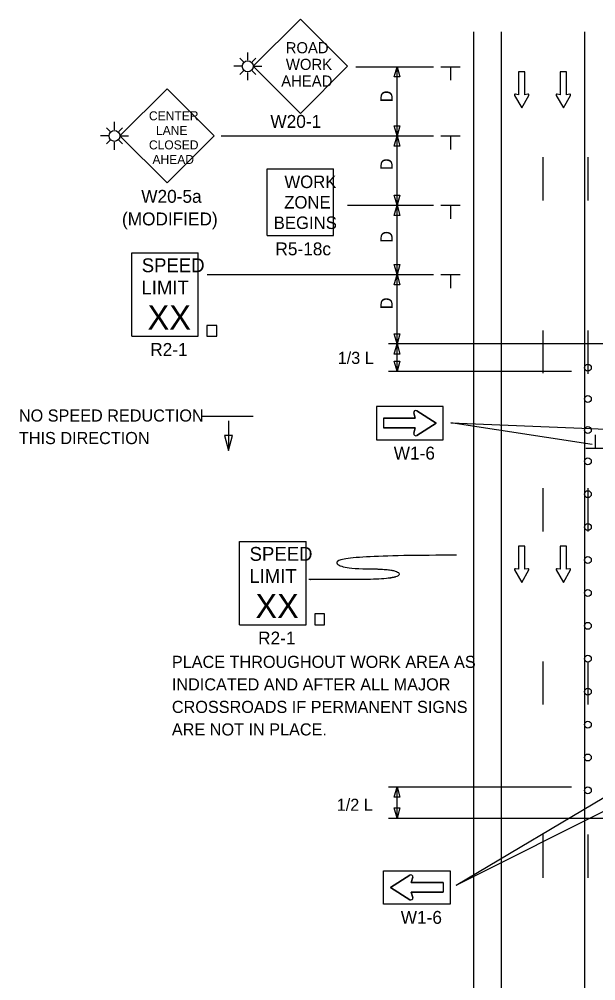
# Model space of a CAD drawing. Extents: x 16525 to 18478, y 5730 to 6925.
# Drawn here: x 16750 to 17082, y 6370 to 6925 of the extents above; entities that cross this region are included whole.
import ezdxf

# ---------------------------------------------------------------- set-up
doc = ezdxf.new("R2010")
doc.units = 0
for name, color, linetype in [('ALI_LEGAL_EX', 7, 'Continuous'), ('Level 3', 7, 'Continuous'), ('MT_SCRATCH_LEVEL_E', 7, 'Continuous'), ('PAVT_EDGE_EX', 7, 'Continuous'), ('TRAFFIC_SIGNS_PR', 7, 'Continuous'), ('TYPICAL_TEXT_DIMEN_PR', 7, 'Continuous')]:
    doc.layers.add(name, color=color, linetype=linetype)

msp = doc.modelspace()

# ---------------------------------------------------------------- linework, layer by layer
at = {"layer": 'ALI_LEGAL_EX'}
for points in [[(17051.59, 6845.22), (17051.59, 6820.22)], [(17077.59, 6845.22), (17077.59, 6820.22)], [(17051.59, 6745.22), (17051.59, 6720.56)], [(17077.59, 6745.22), (17077.59, 6720.22)], [(17051.59, 6654.22), (17051.59, 6629.22)], [(17077.59, 6654.22), (17077.59, 6629.22)], [(17051.59, 6554.22), (17051.59, 6529.22)], [(17077.59, 6554.22), (17077.59, 6529.22)], [(17051.59, 6454.22), (17051.59, 6429.22)], [(17077.59, 6454.22), (17077.59, 6429.22)]]:
    msp.add_lwpolyline(points, dxfattribs=at)
at = {"layer": 'Level 3'}
msp.add_line((17080.12, 6679.35), (16998.62, 6691.92), dxfattribs=at)
at = {"layer": 'MT_SCRATCH_LEVEL_E'}
for p, q in [((17041.26, 6894.53), (17037.52, 6894.53)), ((17037.52, 6894.53), (17037.52, 6881.27)), ((17041.26, 6894.53), (17037.52, 6894.53)), ((17037.52, 6894.53), (17037.52, 6881.27)), ((17041.26, 6881.27), (17041.26, 6894.53)), ((17041.26, 6881.27), (17041.26, 6894.53)), ((17065.33, 6894.53), (17061.59, 6894.53)), ((17061.59, 6894.53), (17061.59, 6881.27)), ((17065.33, 6894.53), (17061.59, 6894.53)), ((17061.59, 6894.53), (17061.59, 6881.27)), ((17065.33, 6881.27), (17065.33, 6894.53)), ((17065.33, 6881.27), (17065.33, 6894.53)), ((17035.26, 6880.9), (17039.41, 6873.66)), ((17035.26, 6880.9), (17039.41, 6873.66)), ((17037.52, 6881.27), (17035.74, 6881.59)), ((17037.52, 6881.27), (17035.74, 6881.59)), ((17039.41, 6873.66), (17043.52, 6880.9)), ((17039.41, 6873.66), (17043.52, 6880.9)), ((17043.03, 6881.59), (17041.26, 6881.27)), ((17043.03, 6881.59), (17041.26, 6881.27)), ((17059.33, 6880.9), (17063.48, 6873.66)), ((17059.33, 6880.9), (17063.48, 6873.66)), ((17061.59, 6881.27), (17059.81, 6881.59)), ((17061.59, 6881.27), (17059.81, 6881.59)), ((17063.48, 6873.66), (17067.59, 6880.9)), ((17063.48, 6873.66), (17067.59, 6880.9)), ((17067.11, 6881.59), (17065.33, 6881.27)), ((17067.11, 6881.59), (17065.33, 6881.27)), ((17041.26, 6620.66), (17037.52, 6620.66)), ((17037.52, 6620.66), (17037.52, 6607.4)), ((17041.26, 6620.66), (17037.52, 6620.66)), ((17037.52, 6620.66), (17037.52, 6607.4)), ((17041.26, 6607.4), (17041.26, 6620.66)), ((17041.26, 6607.4), (17041.26, 6620.66)), ((17065.33, 6620.66), (17061.59, 6620.66)), ((17061.59, 6620.66), (17061.59, 6607.4)), ((17065.33, 6620.66), (17061.59, 6620.66)), ((17061.59, 6620.66), (17061.59, 6607.4)), ((17065.33, 6607.4), (17065.33, 6620.66)), ((17065.33, 6607.4), (17065.33, 6620.66)), ((17035.26, 6607.03), (17039.41, 6599.79)), ((17035.26, 6607.03), (17039.41, 6599.79)), ((17037.52, 6607.4), (17035.74, 6607.72)), ((17037.52, 6607.4), (17035.74, 6607.72)), ((17039.41, 6599.79), (17043.52, 6607.03)), ((17039.41, 6599.79), (17043.52, 6607.03)), ((17043.03, 6607.72), (17041.26, 6607.4)), ((17043.03, 6607.72), (17041.26, 6607.4)), ((17059.33, 6607.03), (17063.48, 6599.79)), ((17059.33, 6607.03), (17063.48, 6599.79)), ((17061.59, 6607.4), (17059.81, 6607.72)), ((17061.59, 6607.4), (17059.81, 6607.72)), ((17063.48, 6599.79), (17067.59, 6607.03)), ((17063.48, 6599.79), (17067.59, 6607.03)), ((17067.11, 6607.72), (17065.33, 6607.4)), ((17067.11, 6607.72), (17065.33, 6607.4))]:
    msp.add_line(p, q, dxfattribs=at)
for centre, start, end in [((17035.67, 6881.13), 80.0362, 209.7731), ((17035.67, 6881.13), 80.0362, 209.7731), ((17043.11, 6881.13), 330.4248, 99.9638), ((17043.11, 6881.13), 330.4248, 99.9638), ((17059.74, 6881.13), 80.0362, 209.7731), ((17059.74, 6881.13), 80.0362, 209.7731), ((17067.18, 6881.13), 330.4248, 99.9638), ((17067.18, 6881.13), 330.4248, 99.9638), ((17035.67, 6607.26), 80.0362, 209.7731), ((17035.67, 6607.26), 80.0362, 209.7731), ((17043.11, 6607.26), 330.4248, 99.9638), ((17043.11, 6607.26), 330.4248, 99.9638), ((17059.74, 6607.26), 80.0362, 209.7731), ((17059.74, 6607.26), 80.0362, 209.7731), ((17067.18, 6607.26), 330.4248, 99.9638), ((17067.18, 6607.26), 330.4248, 99.9638)]:
    msp.add_arc(centre, 0.463, start, end, dxfattribs=at)
at = {"layer": 'PAVT_EDGE_EX'}
for p, q in [((17011.59, 6917.57), (17011.59, 6063.18)), ((17027.59, 6917.57), (17027.59, 6063.18)), ((17075.59, 6917.57), (17075.59, 6063.18))]:
    msp.add_line(p, q, dxfattribs=at)
at = {"layer": 'TRAFFIC_SIGNS_PR'}
for p, q in [((16911.72, 6924.87), (16884.53, 6897.68)), ((16938.9, 6897.68), (16911.72, 6924.87)), ((16881.38, 6901.24), (16881.38, 6905.74)), ((16878.86, 6900.19), (16876.76, 6902.3)), ((16883.89, 6900.19), (16886, 6902.3)), ((16878.22, 6897.68), (16873.39, 6897.68)), ((16878.86, 6895.17), (16876.76, 6893.06)), ((16881.38, 6889.71), (16881.38, 6894.13)), ((16883.89, 6895.17), (16886, 6893.06)), ((16884.53, 6897.68), (16911.72, 6870.49)), ((16884.53, 6897.68), (16889.41, 6897.68)), ((16911.72, 6870.49), (16938.9, 6897.68)), ((16834.77, 6884.67), (16807.62, 6857.51)), ((16861.92, 6857.51), (16834.77, 6884.67)), ((16801.95, 6860.03), (16799.84, 6862.13)), ((16804.47, 6861.07), (16804.47, 6865.57)), ((16806.98, 6860.03), (16809.09, 6862.13)), ((16801.31, 6857.51), (16796.47, 6857.51)), ((16801.95, 6855), (16799.84, 6852.89)), ((16806.98, 6855), (16809.09, 6852.89)), ((16807.62, 6857.51), (16812.5, 6857.51)), ((16807.62, 6857.51), (16834.77, 6830.36)), ((16834.77, 6830.36), (16861.92, 6857.51)), ((16804.47, 6849.55), (16804.47, 6853.96)), ((16892.51, 6800.03), (16892.51, 6838.43)), ((16892.51, 6838.43), (16930.91, 6838.43)), ((16930.91, 6800.03), (16930.91, 6838.43)), ((16892.51, 6800.03), (16930.91, 6800.03)), ((16814.42, 6789.98), (16852.82, 6789.98)), ((16814.42, 6741.98), (16814.42, 6789.98)), ((16852.82, 6741.98), (16852.82, 6789.98)), ((16814.42, 6741.98), (16852.82, 6741.98)), ((16959.64, 6694.55), (16978.04, 6694.55)), ((16959.64, 6694.55), (16959.64, 6688.95)), ((16978.04, 6694.55), (16977.2, 6697.61)), ((16978.88, 6698.86), (16990.04, 6691.75)), ((16978.04, 6688.95), (16959.64, 6688.95)), ((16977.2, 6685.89), (16978.04, 6688.95)), ((16990.04, 6691.75), (16978.88, 6684.65)), ((16876.65, 6623.39), (16915.05, 6623.39)), ((16876.65, 6575.39), (16876.65, 6623.39)), ((16915.05, 6575.39), (16915.05, 6623.39)), ((16876.65, 6575.39), (16915.05, 6575.39)), ((16974.85, 6430.86), (16963.69, 6423.76)), ((16975.69, 6426.56), (16976.53, 6429.62)), ((16963.69, 6423.76), (16974.85, 6416.66)), ((16994.09, 6426.56), (16975.69, 6426.56)), ((16994.09, 6426.56), (16994.09, 6420.96)), ((16976.53, 6417.9), (16975.69, 6420.96)), ((16975.69, 6420.96), (16994.09, 6420.96))]:
    msp.add_line(p, q, dxfattribs=at)
for points in [[(16857.84, 6741.98), (16863.43, 6741.98), (16863.43, 6748.15), (16857.84, 6748.15)], [(16955.64, 6682.15), (16994.04, 6682.15), (16994.04, 6701.35), (16955.64, 6701.35)], [(16920.07, 6575.39), (16925.66, 6575.39), (16925.66, 6581.56), (16920.07, 6581.56)], [(16998.09, 6414.16), (16959.69, 6414.16), (16959.69, 6433.36), (16998.09, 6433.36)]]:
    msp.add_lwpolyline(points, close=True, dxfattribs=at)
for points in [[(16977.2, 6697.61), (16978.04, 6694.55), (16959.64, 6694.55), (16959.64, 6688.95), (16978.04, 6688.95), (16977.2, 6685.89)], [(16978.88, 6684.65), (16990.04, 6691.75), (16978.88, 6698.86)], [(16974.85, 6416.66), (16963.69, 6423.76), (16974.85, 6430.86)], [(16976.53, 6429.62), (16975.69, 6426.56), (16994.09, 6426.56), (16994.09, 6420.96), (16975.69, 6420.96), (16976.53, 6417.9)]]:
    msp.add_lwpolyline(points, dxfattribs=at)
for centre, radius in [((16881.38, 6897.68), 3.15), ((16804.46, 6857.51), 3.15), ((17077.59, 6723.72), 2), ((17077.59, 6705.72), 2), ((17077.59, 6687.72), 2), ((17077.59, 6669.72), 2), ((17077.59, 6650.72), 2), ((17077.59, 6631.72), 2), ((17077.59, 6612.72), 2), ((17077.59, 6593.72), 2), ((17077.59, 6574.72), 2), ((17077.59, 6555.72), 2), ((17077.59, 6536.72), 2), ((17077.59, 6517.72), 2), ((17077.59, 6498.72), 2), ((17077.59, 6479.72), 2)]:
    msp.add_circle(centre, radius, dxfattribs=at)
for centre, start, end in [((16978.28, 6697.91), 57.5304, 195.3269), ((16978.28, 6697.91), 57.5304, 195.3269), ((16978.28, 6685.6), 164.6731, 302.4696), ((16978.28, 6685.6), 164.6731, 302.4696), ((16975.45, 6429.91), 344.6731, 122.4696), ((16975.45, 6429.91), 344.6731, 122.4696), ((16975.45, 6417.6), 237.5304, 15.3269), ((16975.45, 6417.6), 237.5304, 15.3269)]:
    msp.add_arc(centre, 1.12, start, end, dxfattribs=at)
at = {"layer": 'TYPICAL_TEXT_DIMEN_PR'}
for p, q in [((16943.76, 6897.47), (16988.49, 6897.47)), ((16965.92, 6891.61), (16967.49, 6897.47)), ((16967.49, 6897.47), (16969.06, 6891.61)), ((16967.49, 6857.47), (16967.49, 6897.47)), ((16992.74, 6897.47), (17003.99, 6897.47)), ((16998.37, 6897.47), (16998.37, 6889.69)), ((16967.49, 6891.61), (16965.92, 6891.61)), ((16969.06, 6891.61), (16967.49, 6891.61)), ((16967.49, 6857.47), (16965.92, 6863.34)), ((16965.92, 6863.34), (16967.49, 6863.34)), ((16967.49, 6863.34), (16969.06, 6863.34)), ((16969.06, 6863.34), (16967.49, 6857.47)), ((16866.01, 6857.47), (16988.49, 6857.47)), ((16965.92, 6851.61), (16967.49, 6857.47)), ((16967.49, 6817.47), (16967.49, 6857.47)), ((16967.49, 6857.47), (16969.06, 6851.61)), ((16992.74, 6857.47), (17003.99, 6857.47)), ((16998.37, 6857.47), (16998.37, 6849.69)), ((16967.49, 6851.61), (16965.92, 6851.61)), ((16969.06, 6851.61), (16967.49, 6851.61)), ((16967.49, 6817.47), (16965.92, 6823.34)), ((16965.92, 6823.34), (16967.49, 6823.34)), ((16967.49, 6823.34), (16969.06, 6823.34)), ((16969.06, 6823.34), (16967.49, 6817.47)), ((16938.9, 6817.47), (16988.49, 6817.47)), ((16965.92, 6811.61), (16967.49, 6817.47)), ((16967.49, 6817.47), (16969.06, 6811.61)), ((16967.49, 6777.47), (16967.49, 6817.47)), ((16992.74, 6817.47), (17003.99, 6817.47)), ((16998.37, 6817.47), (16998.37, 6809.69)), ((16967.49, 6811.61), (16965.92, 6811.61)), ((16969.06, 6811.61), (16967.49, 6811.61)), ((16967.49, 6777.47), (16965.92, 6783.34)), ((16965.92, 6783.34), (16967.49, 6783.34)), ((16967.49, 6783.34), (16969.06, 6783.34)), ((16969.06, 6783.34), (16967.49, 6777.47)), ((16857.91, 6777.47), (16988.49, 6777.47)), ((16965.92, 6771.61), (16967.49, 6777.47)), ((16967.49, 6777.47), (16969.06, 6771.61)), ((16967.49, 6737.47), (16967.49, 6777.47)), ((16992.74, 6777.47), (17003.99, 6777.47)), ((16998.37, 6777.47), (16998.37, 6769.69)), ((16967.49, 6771.61), (16965.92, 6771.61)), ((16969.06, 6771.61), (16967.49, 6771.61)), ((16967.49, 6737.47), (16965.92, 6743.34)), ((16965.92, 6743.34), (16967.49, 6743.34)), ((16967.49, 6743.34), (16969.06, 6743.34)), ((16969.06, 6743.34), (16967.49, 6737.47)), ((17092.68, 6737.47), (16962.49, 6737.47)), ((16965.92, 6731.61), (16967.49, 6737.47)), ((16967.49, 6721.71), (16967.49, 6737.47)), ((16967.49, 6737.47), (16969.06, 6731.61)), ((16967.49, 6731.61), (16965.92, 6731.61)), ((16967.49, 6721.71), (16965.92, 6727.57)), ((16965.92, 6727.57), (16967.49, 6727.57)), ((16969.06, 6731.61), (16967.49, 6731.61)), ((16967.49, 6727.57), (16969.06, 6727.57)), ((16969.06, 6727.57), (16967.49, 6721.71)), ((16962.49, 6721.72), (17068.12, 6721.72)), ((16884.47, 6695.5), (16855.03, 6695.5)), ((16870.29, 6693), (16870.29, 6675.88)), ((16998.62, 6691.92), (17088.3, 6688.18)), ((16870.29, 6684.67), (16867.94, 6684.67)), ((16867.94, 6684.67), (16870.29, 6675.88)), ((16870.29, 6675.88), (16872.65, 6684.67)), ((16872.65, 6684.67), (16870.29, 6684.67)), ((17082.04, 6677.17), (17082.04, 6684.95)), ((17087.66, 6677.17), (17076.41, 6677.17)), ((17001.57, 6424.99), (17122.68, 6485.78)), ((16962.49, 6481.72), (17068.12, 6481.72)), ((16965.92, 6475.86), (16967.49, 6481.72)), ((16967.49, 6463.75), (16967.49, 6481.72)), ((16967.49, 6481.72), (16969.06, 6475.86)), ((17001.57, 6424.99), (17092.92, 6479.32)), ((16967.49, 6475.86), (16965.92, 6475.86)), ((16969.06, 6475.86), (16967.49, 6475.86)), ((16967.49, 6463.75), (16965.92, 6469.61)), ((16965.92, 6469.61), (16967.49, 6469.61)), ((16967.49, 6469.61), (16969.06, 6469.61)), ((16969.06, 6469.61), (16967.49, 6463.75)), ((16962.49, 6463.75), (17092.12, 6463.75))]:
    msp.add_line(p, q, dxfattribs=at)
msp.add_open_spline([(17001.87, 6615.49), (16932.79, 6615.49), (16932.79, 6607.61), (16968.75, 6607.61), (16968.75, 6601.45), (16920.46, 6601.45), (16916.52, 6601.45)], degree=2, dxfattribs=at)

# ---------------------------------------------------------------- texts
at = {"layer": 'TRAFFIC_SIGNS_PR'}
for s, height, p in [('ROAD', 6.408, (16903.25, 6905.22)), ('WORK', 6.408, (16903.36, 6895.61)), ('AHEAD', 6.408, (16900.66, 6886)), ('CENTER', 5.2, (16824.35, 6866.52)), ('W20-1', 7.449, (16894.4, 6862.17)), ('LANE', 5.2, (16828.42, 6858.12)), ('CLOSED', 5.2, (16824.35, 6849.72)), ('AHEAD', 5.2, (16826.38, 6841.32)), ('WORK', 7.217, (16902.51, 6827.4)), ('W20-5a', 7.44, (16819.91, 6818.92)), ('ZONE', 7.217, (16902.39, 6815.59)), ('(MODIFIED)', 7.44, (16808.77, 6805.88)), ('BEGINS', 7.217, (16896.32, 6803.78)), ('R5-18c', 7.44, (16897.32, 6788.59)), ('SPEED', 8, (16820.19, 6778.84)), ('LIMIT', 8, (16820.03, 6766.04)), ('XX', 14.031, (16823.54, 6745.73)), ('R2-1', 7.44, (16825.1, 6730.53)), ('W1-6', 7.44, (16965.58, 6670.71)), ('SPEED', 8, (16882.42, 6612.25)), ('LIMIT', 8, (16882.26, 6599.45)), ('XX', 14.031, (16885.77, 6579.15)), ('R2-1', 7.44, (16887.33, 6563.95)), ('PLACE THROUGHOUT WORK AREA AS', 7, (16837.58, 6550.43)), ('INDICATED AND AFTER ALL MAJOR', 7, (16837.58, 6537.43)), ('CROSSROADS IF PERMANENT SIGNS', 7, (16837.58, 6524.43)), ('ARE NOT IN PLACE.', 7, (16837.58, 6511.43)), ('W1-6', 7.44, (16969.63, 6402.72))]:
    msp.add_text(s, height=height, dxfattribs=at).set_placement(p)
at = {"layer": 'TYPICAL_TEXT_DIMEN_PR'}
for p in [(16964.93, 6876.93), (16964.93, 6837.75), (16964.93, 6795.84), (16964.93, 6757.5)]:
    msp.add_text('D', height=7, rotation=90, dxfattribs=at).set_placement(p)
for s, p in [('1/3 L', (16933.25, 6725.89)), ('NO SPEED REDUCTION', (16749.31, 6692.62)), ('THIS DIRECTION', (16749.31, 6679.62)), ('1/2 L', (16932.69, 6467.94))]:
    msp.add_text(s, height=7, dxfattribs=at).set_placement(p)

doc.saveas('drawing.dxf')
